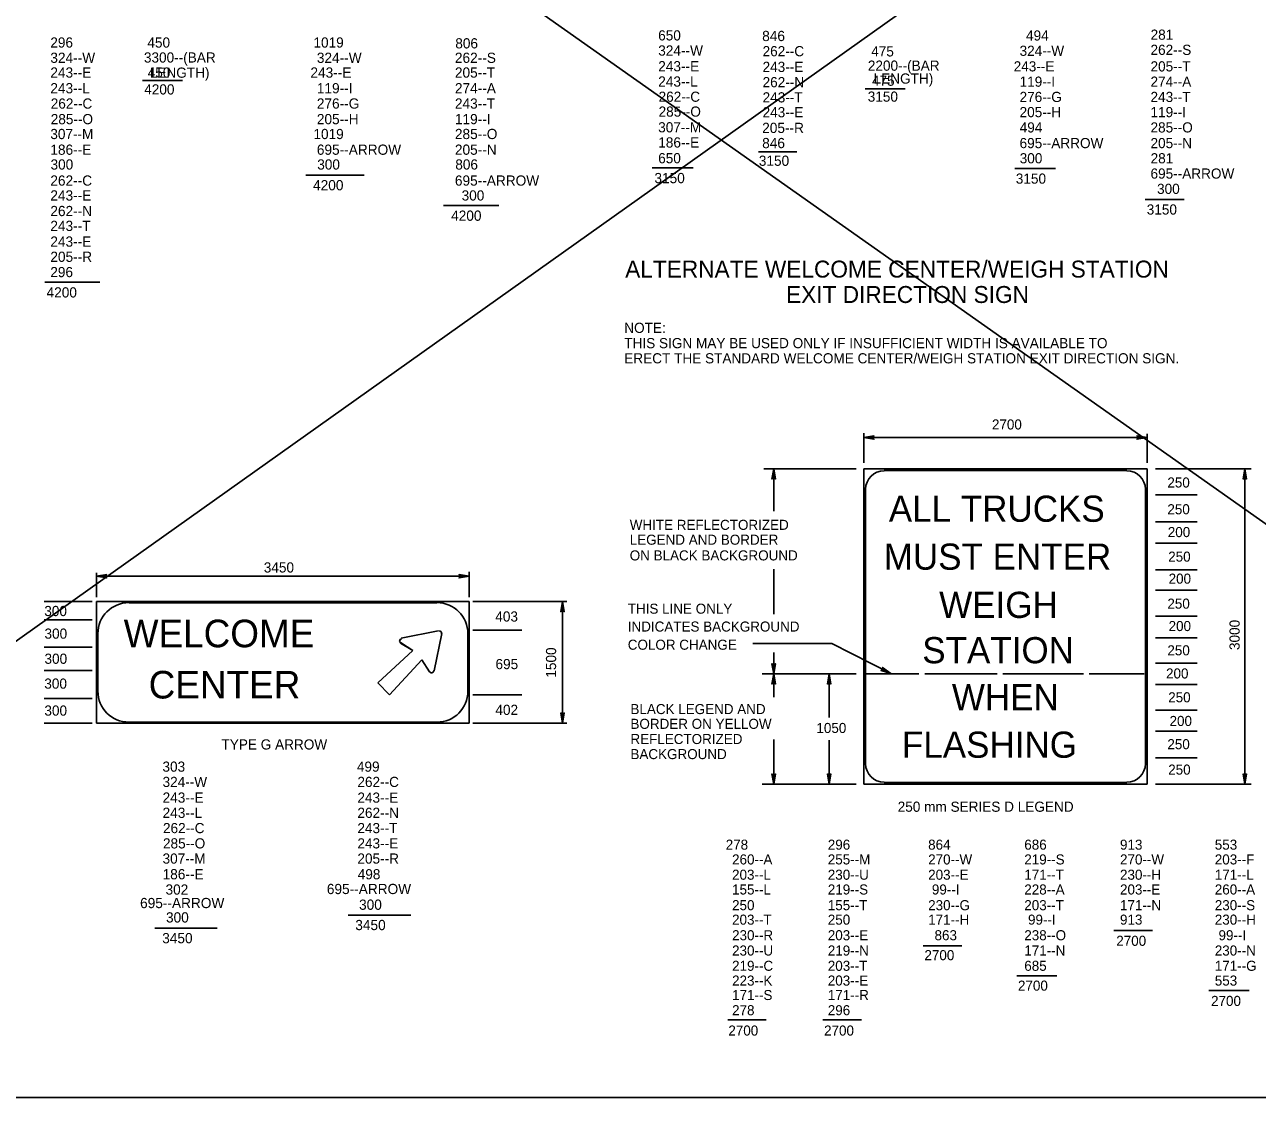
# Model space of a CAD drawing. Extents: x 2189973 to 2192941, y 2147557 to 2151454.
# Drawn here: x 2190678 to 2191872, y 2149535 to 2150594 of the extents above; entities that cross this region are included whole.
import ezdxf

# ---------------------------------------------------------------- set-up
doc = ezdxf.new("R2010")
doc.units = 0
doc.layers.add('1', color=7, linetype='Continuous')
doc.layers.add('Default', color=7, linetype='Continuous')

# ---------------------------------------------------------------- blocks, each defined once
blk = doc.blocks.new('RARROW')
at = {"layer": 'Default'}
blk.add_lwpolyline([(-18.156, 2.28), (-17.479, 0.966), (0, 0), (-18.156, 2.28), (-19.086, 3.077), (0, 0), (-17.465, -0.864), (-18.103, -2.164), (0, 0), (-19.086, -3.033), (-18.103, -2.164)], dxfattribs=at)

msp = doc.modelspace()

# ---------------------------------------------------------------- linework, layer by layer
at = {"layer": '1'}
for p, q in [((2190017.3, 2151423.8), (2192695.6, 2149534.5)), ((2192688.3, 2151431), (2190039.1, 2149549))]:
    msp.add_line(p, q, dxfattribs=at)
at = {"layer": 'Default'}
for p, q in [((2190791.9, 2150539.4), (2190830.7, 2150539.4)), ((2191491.8, 2150531.4), (2191530.7, 2150531.4)), ((2191388.7, 2150470.4), (2191425.7, 2150470.4)), ((2190950.2, 2150447.9), (2191006.8, 2150447.9)), ((2191285.6, 2150454.9), (2191325.2, 2150454.9)), ((2191636.7, 2150454.3), (2191676.2, 2150454.3)), ((2191763, 2150424.4), (2191800.8, 2150424.4)), ((2191083.5, 2150418.4), (2191137.2, 2150418.4)), ((2190697.5, 2150344.2), (2190750.8, 2150344.2)), ((2191490.6, 2150169.2), (2191490.6, 2150197.9)), ((2191765, 2150169.2), (2191765, 2150197.5)), ((2191765, 2150193.8), (2191490.6, 2150193.8)), ((2191483.3, 2150163.4), (2191393.8, 2150163.4)), ((2191403.3, 2150163.4), (2191403.3, 2150122.4)), ((2191490.6, 2150163.4), (2191765, 2150163.4)), ((2191490.6, 2150163.4), (2191490.6, 2149858.3)), ((2191510.3, 2150161.8), (2191745.3, 2150161.8)), ((2191765, 2150163.4), (2191765, 2149858.3)), ((2191773.2, 2150163.4), (2191865.9, 2150163.4)), ((2191859.7, 2150163.4), (2191859.7, 2149858.3)), ((2191492.3, 2149878), (2191492.3, 2150143.7)), ((2191763.4, 2150143.7), (2191763.4, 2149878)), ((2191773.2, 2150138.4), (2191813.4, 2150138.4)), ((2191773.2, 2150112.2), (2191813.4, 2150112.2)), ((2191773.2, 2150091.6), (2191813.4, 2150091.6)), ((2190747.5, 2150039.1), (2190747.5, 2150062.8)), ((2191108.4, 2150039.1), (2191108.4, 2150063.6)), ((2191403.3, 2150066.4), (2191403.3, 2150022.8)), ((2191773.2, 2150065.8), (2191813.4, 2150065.8)), ((2190747.5, 2150059.5), (2191108.4, 2150059.5)), ((2191773.2, 2150046.1), (2191813.4, 2150046.1)), ((2190743.4, 2150035), (2190696.9, 2150035)), ((2190747.5, 2150035), (2191108.4, 2150035)), ((2190747.5, 2150035), (2190747.5, 2149917.3)), ((2191077.2, 2150033.8), (2190779.1, 2150033.8)), ((2191108.4, 2149917.3), (2191108.4, 2150035)), ((2191112.1, 2150035), (2191140.4, 2150035)), ((2191112.1, 2150035), (2191202.9, 2150035)), ((2191198.8, 2149917.3), (2191198.8, 2150035)), ((2190743.4, 2150017.4), (2190696.9, 2150017.4)), ((2191773.2, 2150020.7), (2191813.4, 2150020.7)), ((2190748.8, 2150003.9), (2190748.8, 2149948.1)), ((2191042.4, 2149999.4), (2191078.5, 2150006.7)), ((2191042.4, 2149999.4), (2191078.5, 2150006.7)), ((2191081.8, 2150003.9), (2191074.4, 2149967.8)), ((2191081.8, 2150003.9), (2191074.4, 2149967.8)), ((2191107.2, 2149948.1), (2191107.2, 2150003.9)), ((2191112.1, 2150007.2), (2191159.5, 2150007.2)), ((2191053.9, 2149987.5), (2191042, 2149995.3)), ((2191053.9, 2149987.5), (2191042, 2149994.8)), ((2191459.5, 2149994.5), (2191383.2, 2149994.5)), ((2191516.9, 2149965.3), (2191459.5, 2149994.5)), ((2191773.2, 2149999.8), (2191813.4, 2149999.8)), ((2190743.4, 2149990.7), (2190696.9, 2149990.7)), ((2191019.8, 2149956.3), (2191053.9, 2149987.5)), ((2191019.8, 2149956.3), (2191053.9, 2149987.5)), ((2191403.3, 2149985.8), (2191403.3, 2149964.9)), ((2190743.4, 2149968.2), (2190696.9, 2149968.2)), ((2191062.5, 2149978.4), (2191031.3, 2149944.8)), ((2191062.5, 2149978.4), (2191031.3, 2149944.8)), ((2191069.9, 2149967), (2191062.5, 2149978.4)), ((2191069.9, 2149967), (2191062.5, 2149978.4)), ((2191773.2, 2149975.2), (2191813.4, 2149975.2)), ((2191031.3, 2149944.8), (2191019.8, 2149956.3)), ((2191031.3, 2149944.8), (2191019.8, 2149956.3)), ((2191483.2, 2149964.9), (2191392, 2149964.9)), ((2191403.3, 2149964.9), (2191403.3, 2149942.4)), ((2191457, 2149964.9), (2191457, 2149922.7)), ((2191543.9, 2149964.9), (2191493.1, 2149964.9)), ((2191619.8, 2149964.9), (2191549.7, 2149964.9)), ((2191703.5, 2149964.9), (2191625.1, 2149964.9)), ((2191762.1, 2149964.9), (2191708.8, 2149964.9)), ((2191112.1, 2149944.8), (2191159.5, 2149944.8)), ((2191773.2, 2149954.7), (2191813.4, 2149954.7)), ((2190743.4, 2149941.1), (2190696.9, 2149941.1)), ((2191773.2, 2149929.7), (2191813.4, 2149929.7)), ((2190743.4, 2149917.3), (2190696.9, 2149917.3)), ((2191108.4, 2149917.3), (2190747.5, 2149917.3)), ((2190779.1, 2149918.2), (2191077.2, 2149918.2)), ((2191112.1, 2149917.3), (2191202.9, 2149917.3)), ((2191773.2, 2149909.6), (2191813.4, 2149909.6)), ((2191403.3, 2149901.4), (2191403.3, 2149858.3)), ((2191457, 2149900.9), (2191457, 2149858.3)), ((2191773.2, 2149883.7), (2191813.4, 2149883.7)), ((2191745.3, 2149859.9), (2191510.3, 2149859.9)), ((2191483.3, 2149858.3), (2191392, 2149858.3)), ((2191490.6, 2149858.3), (2191765, 2149858.3)), ((2191773.2, 2149858.3), (2191865.9, 2149858.3)), ((2190991.1, 2149731.2), (2191051.8, 2149731.2)), ((2190804.1, 2149718.8), (2190864.4, 2149718.8)), ((2191732.6, 2149716.4), (2191770.3, 2149716.4)), ((2191548, 2149701.6), (2191585.4, 2149701.6)), ((2191638.7, 2149672.5), (2191677.6, 2149672.5)), ((2191824.9, 2149658.2), (2191863.8, 2149658.2)), ((2191359, 2149629.9), (2191395.9, 2149629.9)), ((2191450.9, 2149629.9), (2191488.2, 2149629.9)), ((2192683.2, 2149554.8), (2190104.5, 2149554.8)), ((2190104.5, 2149554.8), (2192027, 2149554.8))]:
    msp.add_line(p, q, dxfattribs=at)
for centre, radius, start, end in [((2191510.3, 2150143.7), 18, 90, 180), ((2191745.3, 2150143.7), 18, 0, 90), ((2190778.8, 2150003.9), 30, 90, 180), ((2191077.2, 2150003.9), 30, 0, 90), ((2191079.5, 2150004.3), 2.25, 348.2602, 101.7398), ((2191079.5, 2150004.3), 2.25, 348.2602, 101.7398), ((2191043.3, 2149996.8), 2.25, 101.7398, 236.6838), ((2191043.3, 2149996.8), 2.25, 101.7398, 236.6838), ((2191071.9, 2149968.2), 2.25, 213.3162, 348.2602), ((2191071.9, 2149968.2), 2.25, 213.3162, 348.2602), ((2190778.8, 2149948.2), 30, 180, 270), ((2191077.2, 2149948.2), 30, 270, 0), ((2191510.3, 2149878), 18, 180, 270), ((2191745.3, 2149878), 18, 270, 0)]:
    msp.add_arc(centre, radius, start, end, dxfattribs=at)

# ---------------------------------------------------------------- block references
at = {"layer": 'Default', "xscale": 0.515679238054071}
for p, yscale, rotation in [((2191490.6, 2150193.8), 0.5369477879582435, 180), ((2191403.3, 2150163.4), 0.5369477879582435, 89.99999999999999), ((2191859.7, 2150163.4), 0.5369477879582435, 89.99999999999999), ((2190747.5, 2150059.5), 0.5369477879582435, 180), ((2191198.8, 2150035), 0.5369477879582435, 89.99999999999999), ((2191403.3, 2149964.9), 0.5369477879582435, -90.00000000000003), ((2191516.9, 2149965.3), 0.5369477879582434, -26.733042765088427), ((2191403.3, 2149964.9), 0.5369477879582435, 89.99999999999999), ((2191457, 2149964.9), 0.5369477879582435, 89.99999999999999), ((2191198.8, 2149917.3), 0.5369477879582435, -90.00000000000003), ((2191403.3, 2149858.3), 0.5369477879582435, -90.00000000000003), ((2191457, 2149858.3), 0.5369477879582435, -90.00000000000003), ((2191859.7, 2149858.3), 0.5369477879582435, -90.00000000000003)]:
    msp.add_blockref('RARROW', p, dxfattribs=dict(at, yscale=yscale, rotation=rotation))
at = {"layer": 'Default', "xscale": 0.515679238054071, "yscale": 0.5369477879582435}
for p in [(2191765, 2150193.8), (2191108.4, 2150059.5)]:
    msp.add_blockref('RARROW', p, dxfattribs=at)

# ---------------------------------------------------------------- texts
at = {"layer": 'Default'}
for s, height, p in [(' 650   ', 9.84, (2191287.8, 2150578.3)), ('494      ', 9.84, (2191647.7, 2150578.2)), (' 281       ', 9.842, (2191764.7, 2150579)), (' 296   ', 9.84, (2190699.1, 2150571.4)), (' 450               ', 9.842, (2190793.1, 2150571.4)), ('1019       ', 9.842, (2190957.6, 2150571.4)), (' 806       ', 9.842, (2191091.3, 2150570.6)), (' 846   ', 9.89, (2191388.5, 2150577.7)), (' 324--W', 9.89, (2190699.1, 2150556.6)), ('3300--(BAR', 9.84, (2190793.4, 2150556.9)), (' 324--W    ', 9.894, (2190957.2, 2150556.6)), (' 262--S    ', 9.894, (2191090.9, 2150556.6)), (' 324--W', 9.89, (2191287.8, 2150563.6)), (' 262--C', 9.84, (2191388.9, 2150563)), (' 475               ', 9.842, (2191494.1, 2150562.8)), (' 324--W    ', 9.842, (2191637.8, 2150563.4)), (' 262--S    ', 9.842, (2191764.6, 2150564.3)), (' 243--E', 9.89, (2190699.1, 2150542.3)), (' 450               ', 9.842, (2190793.4, 2150542.3)), ('         LENGTH)', 9.842, (2190766.2, 2150542.2)), ('  243--E     ', 9.894, (2190947.3, 2150542.3)), (' 205--T    ', 9.894, (2191090.9, 2150542.3)), (' 243--E', 9.89, (2191287.8, 2150548.4)), (' 243--E', 9.84, (2191388.9, 2150547.8)), ('2200--(BAR', 9.84, (2191494.5, 2150549)), ('  243--E     ', 9.842, (2191628.4, 2150548.3)), (' 205--T    ', 9.842, (2191764.6, 2150548.3)), (' 243--L', 9.89, (2191287.8, 2150533.6)), (' 262--N', 9.84, (2191388.9, 2150533)), (' 475               ', 9.842, (2191494.8, 2150534.4)), ('         LENGTH)', 9.842, (2191467.2, 2150536.5)), (' 119--I    ', 9.842, (2191637.8, 2150533.5)), (' 274--A    ', 9.842, (2191764.6, 2150533.5)), (' 243--L', 9.89, (2190699.1, 2150527.1)), ('4200              ', 9.842, (2190793.7, 2150526)), (' 119--I    ', 9.894, (2190957.2, 2150527.1)), (' 274--A    ', 9.894, (2191090.9, 2150527.1)), (' 262--C', 9.84, (2191288.2, 2150518.9)), (' 243--T', 9.84, (2191388.9, 2150518.3)), ('3150             ', 9.842, (2191494.4, 2150519)), (' 276--G    ', 9.842, (2191637.8, 2150518.7)), (' 243--T    ', 9.842, (2191764.6, 2150518.7)), (' 262--C', 9.84, (2190699.5, 2150512.3)), (' 276--G    ', 9.894, (2190957.2, 2150512.3)), (' 243--T    ', 9.894, (2191090.9, 2150512.3)), (' 285--O', 9.84, (2190699.5, 2150497.2)), (' 205--H    ', 9.894, (2190957.2, 2150497.2)), (' 119--I    ', 9.894, (2191090.9, 2150497.2)), (' 285--O', 9.84, (2191288.2, 2150504.5)), (' 243--E', 9.84, (2191388.9, 2150503.9)), (' 205--H    ', 9.842, (2191637.8, 2150504)), (' 119--I    ', 9.842, (2191764.6, 2150504)), (' 307--M', 9.84, (2190699.1, 2150482.8)), ('1019       ', 9.842, (2190957.6, 2150482.8)), (' 285--O    ', 9.894, (2191090.9, 2150482.8)), (' 307--M', 9.84, (2191287.8, 2150489.3)), (' 205--R', 9.89, (2191388.5, 2150488.7)), (' 494       ', 9.842, (2191637.9, 2150489.2)), (' 285--O    ', 9.842, (2191764.6, 2150489.2)), (' 186--E', 9.89, (2191287.8, 2150474.6)), (' 846   ', 9.89, (2191388.5, 2150474)), (' 695--ARROW', 9.842, (2191637.8, 2150474)), (' 205--N    ', 9.842, (2191764.6, 2150474)), (' 186--E', 9.89, (2190699.1, 2150467.6)), (' 695--ARROW', 9.894, (2190957.2, 2150467.6)), (' 205--N    ', 9.894, (2191090.9, 2150467.6)), (' 650   ', 9.84, (2191287.8, 2150459.4)), (' 300       ', 9.842, (2191637.9, 2150459.3)), (' 281       ', 9.842, (2191764.7, 2150459.3)), (' 300   ', 9.84, (2190699.3, 2150453.3)), (' 300       ', 9.842, (2190957.6, 2150453.3)), (' 806       ', 9.842, (2191091.3, 2150453.3)), ('3150   ', 9.89, (2191388.9, 2150456.9)), (' 262--C', 9.89, (2190699.1, 2150437.7)), (' 695--ARROW', 9.894, (2191090.9, 2150437.7)), ('3150   ', 9.89, (2191287.8, 2150440.1)), ('3150       ', 9.842, (2191637.8, 2150439.6)), (' 695--ARROW', 9.842, (2191764.6, 2150444.5)), (' 243--E', 9.89, (2190699.1, 2150423.3)), ('4200       ', 9.894, (2190957.2, 2150433.2)), ('300      ', 9.84, (2191101.1, 2150423.3)), ('300      ', 9.84, (2191774.6, 2150429.7)), (' 262--N', 9.89, (2190699.1, 2150408.2)), ('4200       ', 9.894, (2191090.9, 2150403.7)), ('3150       ', 9.842, (2191764.6, 2150409.7)), (' 243--T', 9.89, (2190699.1, 2150393.8)), (' 243--E', 9.89, (2190699.1, 2150378.6)), (' 205--R', 9.89, (2190699.1, 2150363.9)), ('ALTERNATE WELCOME CENTER/WEIGH STATION', 16.404, (2191259.5, 2150348.7)), (' 296   ', 9.84, (2190699.1, 2150349.1)), ('4200   ', 9.89, (2190699.1, 2150329.4)), ('EXIT DIRECTION SIGN', 16.404, (2191415.3, 2150324.1)), ('NOTE:', 9.84, (2191258.6, 2150295.1)), ('THIS SIGN MAY BE USED ONLY IF INSUFFICIENT WIDTH IS AVAILABLE TO ', 9.842, (2191258.6, 2150280.3)), ('ERECT THE STANDARD WELCOME CENTER/WEIGH STATION EXIT DIRECTION SIGN.', 9.842, (2191258.6, 2150265.6)), ('2700', 9.73, (2191614.7, 2150201.6)), ('250', 9.73, (2191784.6, 2150145.4)), ('250', 9.73, (2191784.6, 2150119.5)), ('WHITE REFLECTORIZED', 9.732, (2191263.9, 2150104.4)), ('LEGEND AND BORDER', 9.732, (2191263.9, 2150090)), ('200', 9.73, (2191785, 2150097.4)), ('ON BLACK BACKGROUND', 9.732, (2191263.9, 2150074.8)), ('250', 9.73, (2191785.4, 2150073.6)), ('3450', 9.84, (2190909.5, 2150063.1)), ('200', 9.73, (2191785.8, 2150052.3)), ('300', 9.84, (2190696.9, 2150020.9)), ('THIS LINE ONLY', 9.732, (2191262, 2150023.2)), ('250', 9.73, (2191784.6, 2150028.1)), ('403', 9.84, (2191133.7, 2150015.6)), ('INDICATES BACKGROUND', 9.732, (2191262, 2150005.9)), ('200', 9.73, (2191785.8, 2150006.4)), ('300', 9.84, (2190697.1, 2149999)), ('COLOR CHANGE', 9.732, (2191262, 2149988.3)), ('250', 9.73, (2191784.6, 2149982.9)), ('300', 9.84, (2190697.1, 2149974.7)), ('695', 9.84, (2191133.9, 2149969.5)), ('200', 9.73, (2191783.3, 2149960.5)), ('300', 9.84, (2190696.9, 2149950.6)), ('250', 9.73, (2191785.4, 2149937.4)), ('300', 9.84, (2190697, 2149924.5)), ('402', 9.84, (2191133.8, 2149925.2)), ('BLACK LEGEND AND', 9.732, (2191264.6, 2149926)), ('BORDER ON YELLOW', 9.732, (2191264.6, 2149911.7)), ('200', 9.73, (2191786.7, 2149914.5)), ('1050', 9.73, (2191444.7, 2149907.7)), ('TYPE G ARROW', 9.842, (2190868.5, 2149891.7)), ('REFLECTORIZED ', 9.732, (2191264.6, 2149897)), ('250', 9.73, (2191784.6, 2149892)), ('BACKGROUND', 9.73, (2191264.6, 2149882.4)), (' 303 ', 9.84, (2190807.7, 2149870.2)), (' 499   ', 9.84, (2190996, 2149870.2)), ('250', 9.73, (2191785.4, 2149867.4)), (' 324--W', 9.84, (2190807.8, 2149855.4)), (' 262--C', 9.84, (2190996.5, 2149855.4)), (' 243--E', 9.89, (2190807.8, 2149840.2)), (' 243--E', 9.84, (2190996.5, 2149840.2)), ('250 mm SERIES D LEGEND', 9.842, (2191523.4, 2149831.4)), (' 243--L', 9.89, (2190807.8, 2149825.5)), (' 262--N', 9.84, (2190996.5, 2149825.5)), (' 262--C', 9.84, (2190808.2, 2149810.7)), (' 243--T', 9.84, (2190996.5, 2149810.7)), (' 285--O', 9.84, (2190808.2, 2149795.9)), (' 243--E', 9.84, (2190996.5, 2149795.9)), ('  278    ', 9.73, (2191349.6, 2149794.7)), (' 296   ', 9.73, (2191452.1, 2149794.7)), (' 864   ', 9.73, (2191549.3, 2149794.7)), (' 686   ', 9.73, (2191642.4, 2149794.7)), (' 913   ', 9.73, (2191735.1, 2149794.7)), (' 553   ', 9.73, (2191826.9, 2149794.7)), (' 307--M', 9.84, (2190807.8, 2149781.2)), (' 205--R', 9.84, (2190996.5, 2149781.2)), (' 260--A', 9.73, (2191359.4, 2149780.4)), (' 255--M', 9.73, (2191452.1, 2149780.4)), (' 270--W', 9.73, (2191549.3, 2149780.4)), (' 219--S', 9.73, (2191642.4, 2149780.4)), (' 270--W', 9.73, (2191735.1, 2149780.4)), (' 203--F', 9.73, (2191826.9, 2149780.4)), (' 186--E', 9.89, (2190807.8, 2149766)), (' 498  ', 9.84, (2190996.8, 2149766)), (' 203--L', 9.73, (2191359.4, 2149765.6)), (' 230--U', 9.73, (2191452.1, 2149765.6)), (' 203--E', 9.73, (2191549.3, 2149765.6)), (' 171--T', 9.73, (2191642.4, 2149765.6)), (' 230--H', 9.73, (2191735.1, 2149765.6)), (' 171--L', 9.73, (2191826.9, 2149765.6)), (' 302  ', 9.84, (2190810.7, 2149751.2)), ('      695--ARROW', 9.894, (2190948.5, 2149751.7)), (' 155--L', 9.73, (2191359.4, 2149751.3)), (' 219--S', 9.73, (2191452.1, 2149751.3)), ('  99--I', 9.73, (2191549.3, 2149751.3)), (' 228--A', 9.73, (2191642.4, 2149751.3)), (' 203--E', 9.73, (2191735.1, 2149751.3)), (' 260--A', 9.73, (2191826.9, 2149751.3)), ('     695--ARROW', 9.894, (2190771.3, 2149738.1)), (' 300   ', 9.89, (2190998.1, 2149736.5)), (' 250   ', 9.73, (2191359.4, 2149736.1)), (' 155--T', 9.73, (2191452.1, 2149736.1)), (' 230--G', 9.73, (2191549.3, 2149736.1)), (' 203--T', 9.73, (2191642.4, 2149736.1)), (' 171--N', 9.73, (2191735.1, 2149736.1)), (' 230--S', 9.73, (2191826.9, 2149736.1)), (' 300   ', 9.89, (2190811.1, 2149724.2)), (' 203--T', 9.73, (2191359.4, 2149722.1)), (' 250   ', 9.73, (2191452.1, 2149722.1)), (' 171--H', 9.73, (2191549.3, 2149722.1)), ('  99--I', 9.73, (2191642.4, 2149722.1)), (' 913   ', 9.73, (2191735.1, 2149722.1)), (' 230--H', 9.73, (2191826.9, 2149722.1)), ('3450   ', 9.89, (2190998.1, 2149716.8)), (' 230--R', 9.73, (2191359.4, 2149707)), (' 203--E', 9.73, (2191452.1, 2149707)), ('863   ', 9.73, (2191559.1, 2149707)), (' 238--O', 9.73, (2191642.4, 2149707)), ('  99--I', 9.73, (2191826.9, 2149707)), ('3450   ', 9.89, (2190811.1, 2149704.1)), ('2700   ', 9.73, (2191735.1, 2149701.6)), (' 230--U', 9.73, (2191359.4, 2149692.2)), (' 219--N', 9.73, (2191452.1, 2149692.2)), ('2700   ', 9.73, (2191549.3, 2149687.7)), (' 171--N', 9.73, (2191642.4, 2149692.2)), (' 230--N', 9.73, (2191826.9, 2149692.2)), (' 219--C', 9.73, (2191359.4, 2149677.4)), (' 203--T', 9.73, (2191452.1, 2149677.4)), (' 685   ', 9.73, (2191642.4, 2149677.4)), (' 171--G', 9.73, (2191826.9, 2149677.4)), (' 223--K', 9.73, (2191359.4, 2149663.1)), (' 203--E', 9.73, (2191452.1, 2149663.1)), (' 553   ', 9.73, (2191826.9, 2149663.1)), (' 171--S', 9.73, (2191359.4, 2149649.1)), (' 171--R', 9.73, (2191452.1, 2149649.1)), ('2700 ', 9.73, (2191639.9, 2149658.2)), ('2700   ', 9.73, (2191826.9, 2149643.4)), (' 278   ', 9.73, (2191359.4, 2149634.4)), (' 296   ', 9.73, (2191452.1, 2149634.4)), ('2700   ', 9.73, (2191359.4, 2149614.7)), ('2700   ', 9.73, (2191452.1, 2149614.7))]:
    msp.add_text(s, height=height, dxfattribs=at).set_placement(p)
for s, height, rotation, p in [('ALL TRUCKS', 25.35, 360, (2191514.8, 2150112.2)), ('MUST ENTER', 25.35, 360, (2191509.9, 2150065.8)), ('WEIGH', 25.35, 360, (2191563.6, 2150019.1)), ('WELCOME', 26.72, 360, (2190773.8, 2149990.7)), ('3000', 9.84, 90, (2191854.6, 2149988)), ('STATION', 25.35, 360, (2191547.2, 2149975.2)), ('1500', 9.84, 90, (2191192.6, 2149961.3)), ('CENTER', 26.72, 360, (2190798, 2149941.1)), ('WHEN', 25.35, 360, (2191575.9, 2149929.7)), ('FLASHING', 25.35, 360, (2191527.5, 2149883.7))]:
    msp.add_text(s, height=height, rotation=rotation, dxfattribs=at).set_placement(p)

doc.saveas('drawing.dxf')
